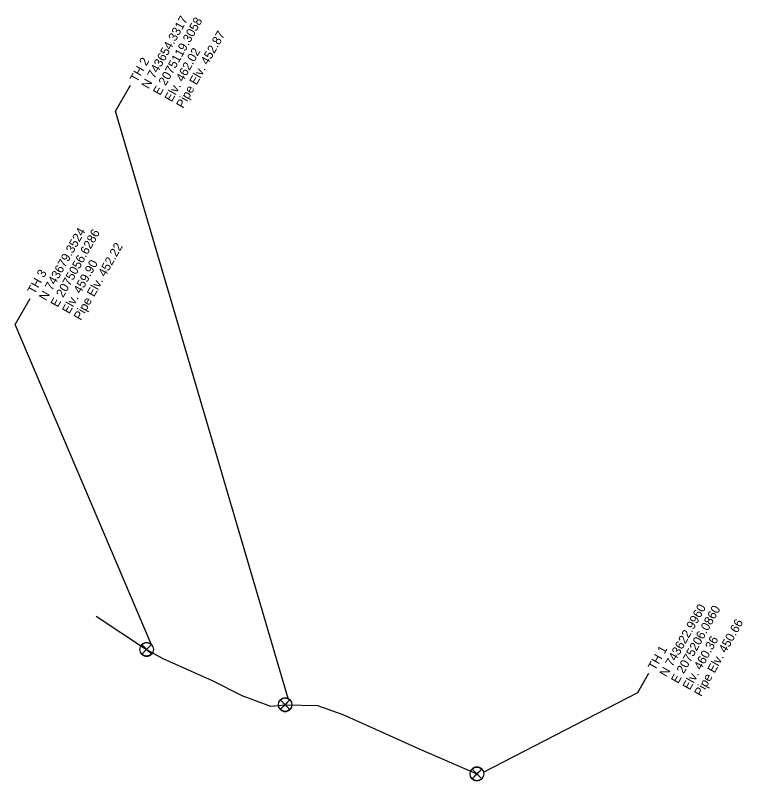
# Model space of a CAD drawing. Extents: x 2074997 to 2075326, y 743620 to 743966.
import ezdxf

# ---------------------------------------------------------------- set-up
doc = ezdxf.new("R2010")
doc.units = 0
for name, color, linetype in [('Prop Conc 2ft 6in Curb and Gutter', 7, 'Continuous'), ('Sheet Block Revision CELL', 7, 'Continuous'), ('Sheet Layout Plan Border', 7, 'Continuous'), ('Sheet Sticker Exception Certification CELL', 7, 'Continuous')]:
    doc.layers.add(name, color=color, linetype=linetype)

msp = doc.modelspace()

# ---------------------------------------------------------------- linework, layer by layer
at = {"layer": 'Prop Conc 2ft 6in Curb and Gutter'}
for points in [[(2075058.8, 743681.53), (2075054.45, 743677.18), (2075056.63, 743679.35), (2075054.45, 743681.53), (2075058.8, 743677.18)], [(2075054.45, 743681.53), (2075056.63, 743679.35), (2075058.8, 743681.53)], [(2075058.8, 743677.18), (2075056.63, 743679.35), (2075054.45, 743677.18)], [(2075121.48, 743656.51), (2075117.13, 743652.16), (2075119.31, 743654.33), (2075117.13, 743656.51), (2075121.48, 743652.16)], [(2075117.13, 743656.51), (2075119.31, 743654.33), (2075121.48, 743656.51)], [(2075121.48, 743652.16), (2075119.31, 743654.33), (2075117.13, 743652.16)], [(2075208.26, 743625.17), (2075203.91, 743620.82), (2075206.09, 743623), (2075203.91, 743625.17), (2075208.26, 743620.82)], [(2075203.91, 743625.17), (2075206.09, 743623), (2075208.26, 743625.17)], [(2075208.26, 743620.82), (2075206.09, 743623), (2075203.91, 743620.82)]]:
    msp.add_lwpolyline(points, dxfattribs=at)
for centre in [(2075056.63, 743679.35), (2075119.31, 743654.33), (2075206.09, 743623)]:
    msp.add_circle(centre, 3.07, dxfattribs=at)
for centre, start, end in [((2075056.63, 743679.35), 45, 135), ((2075056.63, 743679.35), 225, 315), ((2075119.31, 743654.33), 45, 135), ((2075119.31, 743654.33), 225, 315), ((2075206.09, 743623), 45, 135), ((2075206.09, 743623), 225, 315)]:
    msp.add_arc(centre, 3.07, start, end, dxfattribs=at)
at = {"layer": 'Sheet Block Revision CELL'}
for p, q in [((2075042.6, 743922.91), (2075049.28, 743934.74)), ((2075120.69, 743657.08), (2075042.6, 743922.91)), ((2074997.18, 743826.4), (2075003.85, 743838.24)), ((2075058.87, 743681.46), (2074997.18, 743826.4)), ((2075278.92, 743659.82), (2075283.84, 743668.55)), ((2075209.05, 743623.82), (2075278.92, 743659.82))]:
    msp.add_line(p, q, dxfattribs=at)
at = {"layer": 'Sheet Layout Plan Border'}
msp.add_lwpolyline([(2075033.85, 743694.45), (2075056.63, 743679.35), (2075063.88, 743675.27), (2075086.3, 743665.22), (2075099.67, 743658.54), (2075112.64, 743653.62), (2075119.31, 743654.33), (2075133.88, 743653.92), (2075145.48, 743649.84), (2075163.19, 743641.9), (2075179.94, 743634.34), (2075206.09, 743623)], dxfattribs=at)

# ---------------------------------------------------------------- texts
at = {"layer": 'Sheet Sticker Exception Certification CELL'}
for s, p in [('N 743654.3317', (2075057.5, 743932.78)), ('E 2075119.3058', (2075062.72, 743929.83)), ('Pipe Elv. 452.87', (2075073.18, 743923.93)), ('Elv. 462.02', (2075067.95, 743926.88)), ('TH 2', (2075052.27, 743935.72)), ('N 743679.3524', (2075011.12, 743836.86)), ('E 2075056.6286', (2075016.35, 743833.91)), ('Pipe Elv. 452.22', (2075026.8, 743828.02)), ('Elv. 459.90', (2075021.58, 743830.96)), ('TH 3', (2075005.9, 743839.8)), ('N 743622.9960', (2075291.96, 743666.56)), ('E 2075206.0860', (2075297.18, 743663.61)), ('Pipe Elv. 450.66', (2075307.64, 743657.72)), ('Elv. 460.36', (2075302.41, 743660.66)), ('TH 1', (2075286.73, 743669.51))]:
    msp.add_text(s, height=4, rotation=60.5817, dxfattribs=at).set_placement(p)

doc.saveas('drawing.dxf')
